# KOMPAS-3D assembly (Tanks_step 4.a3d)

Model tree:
1. Plane XY
2. Plane ZX
3. Plane ZY
4. X Axis
5. Y Axis
6. Z Axis
7. Origin
8. Polyline:418
9. Polyline:448
10. Polyline:538
11. Polyline:568
12. Polyline:569
13. Polyline:570
14. Route 1  (labels: Route 1)
15. Point:1
     X = -6791.83; Y = -1500; Z = 1.7112e-08; Coordinate.X = -6791.83; Coordinate.Y = -1500; Coordinate.Z = 1.7112e-08
16. Point:2
     X = -1606; Y = -500; Move.X = -500; Distance = 500
17. Point:3
     X = -1606; Y = -2500; Z = 700; Move.X = -500; Move.Z = 4.09273e-09; Distance = 500
18. Polyline:603
19. Polyline:634
20. Attachment Point:1
21. Point:8
     X = -3769.83; Y = -500; Move.Y = 1000; Distance = 1000
22. Point:9
     X = -3769.83; Y = 762.724; Z = 3112; Move.Z = 500; Distance = 500
23. Polyline:757
24. Route (150mm)  (labels: Route (150mm); C:\Program Files\ASCON\KOMPAS-3D V10\Sys\graphic.lyt; Pipe Dn 50; Pipe_Tanks_step 2_70.m3d)
     Orientation = 2; Orientation = 1; Orientation = 1; Orientation = 1; Orientation = 1; Orientation = 1; Orientation = 1; Orientation = 1; Orientation = 1; Orientation = 1; Orientation = 1; Orientation = 1; Orientation = 1; Orientation = 1

Referenced files in C:\Documents and Settings\kashirsky\Мои документы\Camtasia Studio\Pipelines3D\Tanks\: Tank 2.a3d, Tank 1.a3d, Piping_Joint_150_1000.m3d, Piping_Flange_150_1000.m3d, Piping_Joint_50_1000.m3d, Piping_Flange_50_1000.m3d
Referenced files in C:\Program Files\ASCON\KOMPAS-3D V10\Libs\Piping\Equipment\Valve\: Piping_Valve_50_1000.m3d
Referenced files in C:\Program Files\ASCON\KOMPAS-3D V10\Libs\Piping\LOAD\: Piping_C_Bend_90_50_1000.m3d, Piping_C_TBend_50_1000.m3d
Referenced files in C:\Documents and Settings\kashirsky\Мои документы\Camtasia Studio\Pipelines3D\Tanks\Tanks_step 2_Pipes\: Pipe_Tanks_step 2_70.m3d, Pipe_Tanks_step 2_71.m3d, Pipe_Tanks_step 2_72.m3d, Pipe_Tanks_step 2_73.m3d, Pipe_Tanks_step 2_74.m3d, Pipe_Tanks_step 2_75.m3d, Pipe_Tanks_step 2_76.m3d, Pipe_Tanks_step 2_77.m3d, Pipe_Tanks_step 2_78.m3d, Pipe_Tanks_step 2_79.m3d, Pipe_Tanks_step 2_80.m3d, Pipe_Tanks_step 2_81.m3d, Pipe_Tanks_step 2_82.m3d, Pipe_Tanks_step 2_83.m3d, Pipe_Tanks_step 2_84.m3d, Pipe_Tanks_step 2_85.m3d, Pipe_Tanks_step 2_86.m3d, Pipe_Tanks_step 2_87.m3d, Pipe_Tanks_step 2_88.m3d, Pipe_Tanks_step 2_89.m3d
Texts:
  Three Point Plane
  Plane at Angle
  Line and Point Plane
  Axis through Two Vertices
  Axis of Feature
  Axis of Conical Surface
  Axis through Edge
  Trim by Surface
  Trim by Sketch
  Intersection Axis of Two Planes
  Two Line Plane
  Line and Face Plane
  Pattern by Sample
  Point in CM
  Feature with No History
  Linear Dimension from Line to Point
  Surface Finish Symbol
  Geometric Tolerance Symbol
  Текст на чертеже
  Линия-выноска #1
  Линия-выноска #2
  Линия-выноска #3
  Отклонения формы и база
  Марка координационной оси
  Марка/позиционное обозначение с линией-выноской
  Марка/позиционное обозначение на линии
  Марка/позиционное обозначение без линии-выноски
  Tank 2
  Tank 1
  Joint Dn 150
  Steel ASTM A295
  Flange Dn 150
  Прокладка Dy 50
  Flange Dn 50
  Bend 90 Dn 50
  T-Bend Dn 50
  Трубы - объекты
  Pipe Dn 50
  Трубы - описания
  Элементы - объекты
  Элементы - описания
  Pipelines 3D
  Valve Dy 50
